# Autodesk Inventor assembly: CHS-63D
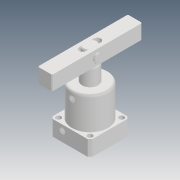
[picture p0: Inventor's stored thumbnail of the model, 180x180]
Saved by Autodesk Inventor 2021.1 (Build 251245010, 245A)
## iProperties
Created: 2019-05
Part Number: CHS-63D
Description: STEP AP203
Document SubType Name: Assembly
Designer: user
Title: chs-63d_asm.STEP
Revision Number: ÈÎºÎ
Sending System: SolidWorks 2017
Preprocessor: SwSTEP 2.0
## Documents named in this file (6)
- D:\Vault_2016\Projekty\Clamptek\Hydraulic\CHS\CHS-63\Inventor\CHS-63D\CHS-63D.iam
- D:\Vault_2016\Projekty\Clamptek\Hydraulic\CHS\CHS-63\Inventor\CHS-63D\CHS-63-03.ipt
- D:\Vault_2016\Projekty\Clamptek\Hydraulic\CHS\CHS-63\Inventor\CHS-63D\CHS-63D-01_4.ipt
- D:\Vault_2016\Projekty\Clamptek\Hydraulic\CHS\CHS-63\Inventor\CHS-63D\CHS-63D»îÈû¸Ë.ipt
- D:\Vault_2016\Projekty\Clamptek\Hydraulic\CHS\CHS-63\Inventor\CHS-63D\¶ÌÏú.ipt
- D:\Vault_2016\Projekty\Clamptek\Hydraulic\CHS\CHS-63\Inventor\CHS-63D\¿¨»É.ipt
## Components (6 placed, 6 different names)
1. CHS-63-03_1
2. CHS-63D-01_4_2
3. CHS-63D»îÈû¸Ë_3
4. ¶ÌÏú_4
5. ¿¨»É_5
6. ¿¨»É_6
